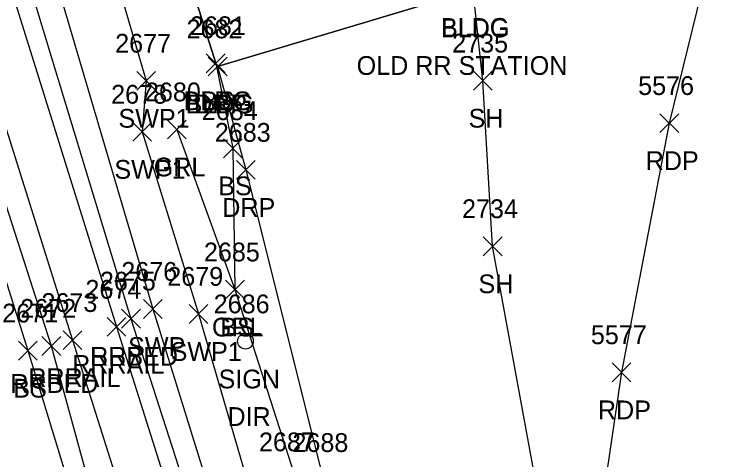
# Model space of a CAD drawing. Extents: x 1462668 to 1465147, y 550359 to 557351.
# Drawn here: x 1464246.9 to 1464321.7, y 553768.4 to 553815.9 of the extents above; entities that cross this region are included whole.
import ezdxf

# ---------------------------------------------------------------- set-up
doc = ezdxf.new("R2010")
doc.units = 0
for name, color, linetype in [('L_A', 7, 'Continuous'), ('L_C', 7, 'Continuous'), ('L_I', 7, 'Continuous'), ('L_TIC', 7, 'Continuous'), ('LBC', 7, 'Continuous'), ('LELB', 7, 'Continuous'), ('Level 6', 7, 'Continuous'), ('P_A', 7, 'Continuous'), ('P_I', 7, 'Continuous'), ('P_TIC', 7, 'Continuous'), ('PET', 7, 'Continuous'), ('R_A', 7, 'Continuous'), ('R_I', 7, 'Continuous'), ('R_TIC', 7, 'Continuous'), ('RDP', 7, 'Continuous'), ('RGR', 7, 'Continuous'), ('RR', 7, 'Continuous'), ('RRB', 7, 'Continuous'), ('RSW', 7, 'Continuous'), ('S_A', 7, 'Continuous'), ('S_C', 7, 'Continuous'), ('S_I', 7, 'Continuous'), ('SSGN', 7, 'Continuous')]:
    doc.layers.add(name, color=color, linetype=linetype)

msp = doc.modelspace()

# ---------------------------------------------------------------- linework, layer by layer
at = {"layer": 'L_TIC'}
for points in [[(1464267.355, 553809.698), (1464269.355, 553811.698)], [(1464269.355, 553809.698), (1464267.355, 553811.698)], [(1464267.355, 553809.698), (1464269.355, 553811.698)], [(1464269.355, 553809.698), (1464267.355, 553811.698)], [(1464267.562, 553809.36), (1464269.562, 553811.36)], [(1464269.562, 553809.36), (1464267.562, 553811.36)], [(1464295.796, 553807.846), (1464297.796, 553809.846)], [(1464297.796, 553807.846), (1464295.796, 553809.846)], [(1464269.181, 553800.643), (1464271.181, 553802.643)], [(1464271.181, 553800.643), (1464269.181, 553802.643)], [(1464296.845, 553790.204), (1464298.845, 553792.204)], [(1464298.845, 553790.204), (1464296.845, 553792.204)], [(1464269.41, 553785.596), (1464271.41, 553787.596)], [(1464271.41, 553785.596), (1464269.41, 553787.596)], [(1464247.361, 553779.086), (1464249.361, 553781.086)], [(1464249.361, 553779.086), (1464247.361, 553781.086)]]:
    msp.add_lwpolyline(points, dxfattribs=at)
at = {"layer": 'LBC'}
msp.add_lwpolyline([(1464235.966, 553936.39), (1464239.309, 553926.386), (1464240.796, 553921.806), (1464245.894, 553905.569), (1464247.499, 553900.468), (1464254.832, 553878.637), (1464247.829, 553876.435), (1464257.997, 553843.531), (1464268.355, 553810.698), (1464268.562, 553810.36), (1464295.738, 553818.515)], dxfattribs=at)
at = {"layer": 'LELB'}
for points in [[(1464149.816, 554097.705), (1464160.815, 554058.944), (1464174.588, 554016.825), (1464187.841, 553973.144), (1464199.911, 553935.221), (1464213.639, 553890.918), (1464230.859, 553835.646), (1464248.361, 553780.086), (1464256.018, 553754.978), (1464244.973, 553761.44)], [(1464268.355, 553810.698), (1464270.181, 553801.643), (1464270.41, 553786.596)]]:
    msp.add_lwpolyline(points, dxfattribs=at)
at = {"layer": 'Level 6'}
for points in [[(1464295.738, 553818.515), (1464268.562, 553810.36), (1464268.355, 553810.698), (1464257.997, 553843.531)], [(1464308.788, 553693.793), (1464308.334, 553703.599), (1464307.879, 553713.405), (1464307.957, 553719.403), (1464308.034, 553725.401), (1464308.112, 553731.398), (1464308.189, 553737.396), (1464308.095, 553745.535), (1464308.002, 553753.674), (1464303.066, 553762.592), (1464297.845, 553791.204), (1464296.796, 553808.846), (1464295.764, 553818.462)]]:
    msp.add_lwpolyline(points, dxfattribs=at)
at = {"layer": 'P_TIC'}
for points in [[(1464315.654, 553803.321), (1464317.654, 553805.321)], [(1464317.654, 553803.321), (1464315.654, 553805.321)], [(1464310.565, 553776.777), (1464312.565, 553778.777)], [(1464312.565, 553776.777), (1464310.565, 553778.777)]]:
    msp.add_lwpolyline(points, dxfattribs=at)
at = {"layer": 'PET'}
msp.add_lwpolyline([(1464359.479, 554043.269), (1464359.177, 554029.074), (1464357.956, 554009.095), (1464355, 553971.723), (1464354.556, 553966.426), (1464353.903, 553966.424), (1464345.393, 553923.728), (1464333.428, 553874.159), (1464323.524, 553832.396), (1464316.654, 553804.321), (1464311.565, 553777.777), (1464308.002, 553753.674)], dxfattribs=at)
at = {"layer": 'R_TIC'}
for points in [[(1464267.562, 553809.36), (1464269.562, 553811.36)], [(1464269.562, 553809.36), (1464267.562, 553811.36)], [(1464259.962, 553807.835), (1464261.962, 553809.835)], [(1464261.962, 553807.835), (1464259.962, 553809.835)], [(1464259.53, 553802.397), (1464261.53, 553804.397)], [(1464261.53, 553802.397), (1464259.53, 553804.397)], [(1464263.217, 553802.647), (1464265.217, 553804.647)], [(1464265.217, 553802.647), (1464263.217, 553804.647)], [(1464270.566, 553798.338), (1464272.566, 553800.338)], [(1464272.566, 553798.338), (1464270.566, 553800.338)], [(1464269.41, 553785.596), (1464271.41, 553787.596)], [(1464271.41, 553785.596), (1464269.41, 553787.596)], [(1464260.667, 553783.525), (1464262.667, 553785.525)], [(1464262.667, 553783.525), (1464260.667, 553785.525)], [(1464265.515, 553782.995), (1464267.515, 553784.995)], [(1464267.515, 553782.995), (1464265.515, 553784.995)], [(1464258.336, 553782.492), (1464260.336, 553784.492)], [(1464260.336, 553782.492), (1464258.336, 553784.492)], [(1464256.79, 553781.617), (1464258.79, 553783.617)], [(1464258.79, 553781.617), (1464256.79, 553783.617)], [(1464252.11, 553780.209), (1464254.11, 553782.209)], [(1464254.11, 553780.209), (1464252.11, 553782.209)], [(1464249.852, 553779.587), (1464251.852, 553781.587)], [(1464251.852, 553779.587), (1464249.852, 553781.587)]]:
    msp.add_lwpolyline(points, dxfattribs=at)
at = {"layer": 'RDP'}
msp.add_lwpolyline([(1464268.562, 553810.36), (1464271.566, 553799.338), (1464279.834, 553766.292), (1464281.391, 553761.499), (1464281.997, 553758.855), (1464283.639, 553754.279), (1464287.494, 553741.64), (1464290.385, 553733.2), (1464305.314, 553737.262), (1464306.465, 553737.226), (1464308.189, 553737.396)], dxfattribs=at)
at = {"layer": 'RGR'}
msp.add_lwpolyline([(1464264.217, 553803.647), (1464270.41, 553786.596), (1464281.139, 553753.131), (1464287.424, 553732.203), (1464290.756, 553720.464)], dxfattribs=at)
at = {"layer": 'RR'}
for points in [[(1464159.204, 554098.673), (1464170.624, 554062.013), (1464183.918, 554019.066), (1464196.892, 553977.392), (1464209.212, 553938.085), (1464222.641, 553894.356), (1464240.124, 553839.141), (1464257.79, 553782.617), (1464270.965, 553740.903), (1464277.927, 553719.147), (1464297.823, 553655.397), (1464314.573, 553602.418), (1464329.227, 553555.383), (1464346.959, 553499.526)], [(1464154.284, 554097.878), (1464165.905, 554060.669), (1464179.184, 554017.63), (1464192.387, 553975.365), (1464204.49, 553936.135), (1464218.059, 553892.735), (1464235.464, 553837.337), (1464253.11, 553781.209), (1464266.289, 553739.573), (1464273.101, 553717.548), (1464293.091, 553653.685), (1464309.879, 553600.873), (1464324.555, 553553.944), (1464342.167, 553498.072)]]:
    msp.add_lwpolyline(points, dxfattribs=at)
at = {"layer": 'RRB'}
for points in [[(1464161.709, 554099.45), (1464173.808, 554063.103), (1464186.023, 554019.884), (1464199.38, 553978.333), (1464209.401, 553949.713), (1464214.23, 553929.585), (1464224.651, 553895.04), (1464242.268, 553839.512), (1464259.336, 553783.492), (1464272.854, 553741.47), (1464279.492, 553719.79), (1464299.296, 553656.238), (1464316.436, 553603.185), (1464331.592, 553556.577), (1464345.31, 553519.908), (1464352.279, 553501.122)], [(1464151.795, 554097.772), (1464163.731, 554059.699), (1464177.169, 554017.629), (1464190.458, 553974.22), (1464202.507, 553935.726), (1464215.786, 553891.787), (1464232.833, 553836.506), (1464250.852, 553780.587), (1464262.352, 553738.507), (1464269.731, 553716.507), (1464275.238, 553698.116), (1464287.034, 553660.877), (1464293.496, 553639.155), (1464306.315, 553607.258), (1464308.598, 553599.833), (1464319.366, 553564.191), (1464320.567, 553552.858), (1464339.05, 553497.299)]]:
    msp.add_lwpolyline(points, dxfattribs=at)
at = {"layer": 'RSW'}
for points in [[(1464216.42, 553930.173), (1464227.233, 553895.778), (1464245.198, 553840.268), (1464261.667, 553784.525), (1464272.016, 553751.171), (1464275.268, 553741.868), (1464279.112, 553743.041)], [(1464247.499, 553900.468), (1464234.828, 553895.87), (1464251.277, 553841.942), (1464260.962, 553808.835), (1464260.53, 553803.397), (1464266.515, 553783.995), (1464275.793, 553752.205), (1464279.112, 553743.041)]]:
    msp.add_lwpolyline(points, dxfattribs=at)
at = {"layer": 'SSGN'}
for p, q in [((1464269.877, 553781.92), (1464273.21, 553781.92)), ((1464271.524, 553781.086), (1464271.524, 553781.086))]:
    msp.add_line(p, q, dxfattribs=at)
msp.add_circle((1464271.524, 553781.086), 0.833, dxfattribs=at)

# ---------------------------------------------------------------- texts
at = {"layer": 'L_A'}
for s, p in [('BLDG', (1464292.328, 553813.515)), ('BLDG', (1464292.355, 553813.462)), ('BLDG', (1464264.946, 553805.698)), ('BLDG', (1464265.152, 553805.36)), ('BS', (1464266.796, 553805.698)), ('SH', (1464295.284, 553803.846)), ('BS', (1464268.622, 553796.643)), ('SH', (1464296.333, 553786.204)), ('BS', (1464268.851, 553781.596)), ('BS', (1464246.802, 553775.086))]:
    msp.add_text(s, height=2, dxfattribs=at).set_placement(p)
at = {"layer": 'L_C'}
msp.add_text('OLD RR STATION', height=2, dxfattribs=at).set_placement((1464283.363, 553809.462))
at = {"layer": 'L_I'}
for s, p in [('2681', (1464265.615, 553813.698)), ('2681', (1464265.615, 553813.698)), ('2682', (1464265.255, 553813.36)), ('2735', (1464293.536, 553811.846)), ('2684', (1464266.874, 553804.643)), ('2734', (1464294.585, 553794.204)), ('2685', (1464267.103, 553789.596)), ('2671', (1464245.621, 553783.086))]:
    msp.add_text(s, height=2, dxfattribs=at).set_placement(p)
at = {"layer": 'P_A'}
for p in [(1464314.142, 553799.321), (1464309.053, 553772.777)]:
    msp.add_text('RDP', height=2, dxfattribs=at).set_placement(p)
at = {"layer": 'P_I'}
for s, p in [('5576', (1464313.339, 553807.321)), ('5577', (1464308.305, 553780.777))]:
    msp.add_text(s, height=2, dxfattribs=at).set_placement(p)
at = {"layer": 'R_A'}
for s, p in [('DRP', (1464266.05, 553805.36)), ('SWP1', (1464258.001, 553803.835)), ('GRL', (1464261.76, 553798.647)), ('SWP1', (1464257.569, 553798.397)), ('DRP', (1464269.054, 553794.338)), ('GRL', (1464267.953, 553781.596)), ('SWP', (1464259.03, 553779.525)), ('RRBED', (1464254.982, 553778.492)), ('SWP1', (1464263.555, 553778.995)), ('RRRAIL', (1464253.081, 553777.617)), ('RRRAIL', (1464248.401, 553776.209)), ('RRBED', (1464246.498, 553775.587))]:
    msp.add_text(s, height=2, dxfattribs=at).set_placement(p)
at = {"layer": 'R_I'}
for s, p in [('2682', (1464265.255, 553813.36)), ('2677', (1464257.654, 553811.835)), ('2678', (1464257.223, 553806.397)), ('2680', (1464260.823, 553806.647)), ('2683', (1464268.259, 553802.338)), ('2685', (1464267.103, 553789.596)), ('2676', (1464258.305, 553787.525)), ('2679', (1464263.201, 553786.995)), ('2675', (1464256.029, 553786.492)), ('2674', (1464254.483, 553785.617)), ('2673', (1464249.803, 553784.209)), ('2672', (1464247.545, 553783.587)), ('2688', (1464276.527, 553769.292)), ('2688', (1464276.527, 553769.292))]:
    msp.add_text(s, height=2, dxfattribs=at).set_placement(p)
at = {"layer": 'S_A'}
msp.add_text('SIGN', height=2, dxfattribs=at).set_placement((1464268.661, 553776.066))
at = {"layer": 'S_C'}
msp.add_text('DIR', height=2, dxfattribs=at).set_placement((1464269.606, 553772.066))
at = {"layer": 'S_I'}
for s, p in [('2686', (1464268.142, 553784.066)), ('2687', (1464272.966, 553769.367))]:
    msp.add_text(s, height=2, dxfattribs=at).set_placement(p)

doc.saveas('drawing.dxf')
